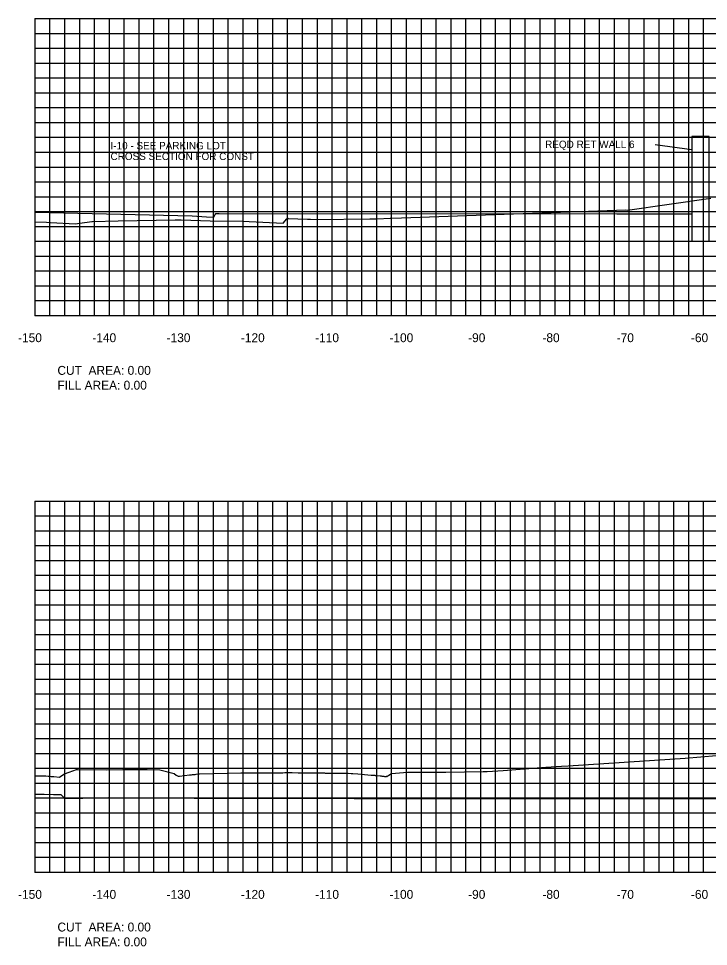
# Model space of a CAD drawing. Extents: x 1800880 to 1814006, y 250083 to 250560.
# Drawn here: x 1811658.8 to 1811751.7, y 250089.4 to 250214.4 of the extents above; entities that cross this region are included whole.
import ezdxf

# ---------------------------------------------------------------- set-up
doc = ezdxf.new("R2010")
doc.units = 0
for name, color, linetype in [('CL-CNST', 7, 'Continuous'), ('DESIGN - DRAINAGE - Bridges', 7, 'Continuous'), ('DRAINAGETXT', 7, 'Continuous'), ('EPTEXT', 7, 'Continuous'), ('Level 46', 7, 'Continuous'), ('Level 62', 7, 'Continuous')]:
    doc.layers.add(name, color=color, linetype=linetype)

msp = doc.modelspace()

# ---------------------------------------------------------------- linework, layer by layer
at = {"layer": 'CL-CNST'}
for points in [[(1811661, 250187.06), (1811662.51, 250186.98), (1811663.08, 250186.96), (1811666.44, 250186.78), (1811666.96, 250186.88), (1811667.04, 250186.87), (1811668.63, 250187.08), (1811668.72, 250187.08), (1811672.16, 250187.2), (1811679.86, 250187.32), (1811680.02, 250187.32), (1811680.68, 250187.3), (1811684.57, 250187.17), (1811688.92, 250187.12), (1811694.39, 250186.86), (1811694.89, 250187.45), (1811694.99, 250187.53), (1811695.02, 250187.53), (1811695.03, 250187.52), (1811695.05, 250187.49), (1811697.68, 250187.4), (1811698.08, 250187.39), (1811699.02, 250187.36), (1811706.06, 250187.45), (1811706.54, 250187.45), (1811707.03, 250187.45), (1811708.79, 250187.54), (1811708.87, 250187.54), (1811710.35, 250187.6), (1811740.52, 250188.64), (1811740.75, 250188.63), (1811751.98, 250190.23)], [(1811661, 250112.39), (1811661.42, 250112.39), (1811661.63, 250112.39), (1811662.39, 250112.38), (1811662.46, 250112.38), (1811662.74, 250112.36), (1811662.97, 250112.34), (1811663.16, 250112.33), (1811663.24, 250112.32), (1811663.29, 250112.32), (1811663.38, 250112.31), (1811663.45, 250112.3), (1811663.52, 250112.29), (1811664.28, 250112.22), (1811664.47, 250112.36), (1811664.95, 250112.68), (1811665.6, 250112.9), (1811666.57, 250113.24), (1811666.69, 250113.25), (1811670.61, 250113.2), (1811672.83, 250113.24), (1811672.93, 250113.24), (1811674.73, 250113.24), (1811675.11, 250113.24), (1811675.3, 250113.25), (1811676.04, 250113.25), (1811676.1, 250113.26), (1811677.79, 250113.19), (1811679.74, 250112.73), (1811680, 250112.49), (1811680.28, 250112.34), (1811680.34, 250112.34), (1811680.46, 250112.35), (1811681.77, 250112.52), (1811681.95, 250112.54), (1811681.98, 250112.54), (1811682.07, 250112.54), (1811682.2, 250112.59), (1811682.24, 250112.59), (1811682.35, 250112.58), (1811682.51, 250112.57), (1811682.56, 250112.58), (1811682.7, 250112.62), (1811682.98, 250112.65), (1811683.12, 250112.67), (1811688.7, 250112.79), (1811690.25, 250112.82), (1811690.32, 250112.82), (1811690.69, 250112.82), (1811690.75, 250112.82), (1811690.98, 250112.82), (1811691.19, 250112.82), (1811691.2, 250112.82), (1811691.22, 250112.82), (1811691.23, 250112.82), (1811691.24, 250112.82), (1811691.26, 250112.82), (1811691.65, 250112.82), (1811694.33, 250112.81), (1811694.64, 250112.83), (1811694.78, 250112.83), (1811694.96, 250112.83), (1811695.59, 250112.84), (1811696.42, 250112.81), (1811699.94, 250112.79), (1811700.04, 250112.78), (1811700.38, 250112.77), (1811700.85, 250112.77), (1811700.96, 250112.77), (1811701.34, 250112.75), (1811701.55, 250112.75), (1811702.12, 250112.76), (1811702.5, 250112.76), (1811703, 250112.74), (1811703.13, 250112.74), (1811703.54, 250112.72), (1811703.76, 250112.72), (1811704.47, 250112.67), (1811706.23, 250112.5), (1811706.72, 250112.47), (1811706.74, 250112.47), (1811706.75, 250112.47), (1811706.79, 250112.46), (1811706.82, 250112.46), (1811706.84, 250112.46), (1811706.88, 250112.46), (1811706.92, 250112.46), (1811706.95, 250112.45), (1811706.98, 250112.45), (1811707.01, 250112.45), (1811707.44, 250112.39), (1811707.58, 250112.38), (1811707.7, 250112.36), (1811707.82, 250112.35), (1811707.93, 250112.34), (1811708.03, 250112.33), (1811708.13, 250112.32), (1811708.22, 250112.31), (1811708.29, 250112.3), (1811708.3, 250112.32), (1811708.34, 250112.39), (1811708.37, 250112.3), (1811708.63, 250112.48), (1811709, 250112.72), (1811711.12, 250112.91), (1811715.93, 250112.9), (1811716.07, 250112.9), (1811716.29, 250112.9), (1811721.32, 250113), (1811721.39, 250113), (1811721.84, 250113), (1811724.02, 250113.13), (1811729.75, 250113.55), (1811731.86, 250113.7), (1811732.75, 250113.76), (1811748.54, 250114.79), (1811754.84, 250115.33)]]:
    msp.add_lwpolyline(points, dxfattribs=at)
at = {"layer": 'DESIGN - DRAINAGE - Bridges'}
for p, q in [((1811660.94, 250214.43), (1811661, 250214.43)), ((1811661, 250174.43), (1811661, 250214.43)), ((1811660.94, 250204.43), (1811661, 250204.43)), ((1811660.94, 250194.43), (1811661, 250194.43)), ((1811660.94, 250184.43), (1811661, 250184.43)), ((1811660.94, 250174.43), (1811661, 250174.43)), ((1811661, 250174.43), (1811961, 250174.43)), ((1811661, 250174.37), (1811661, 250174.43)), ((1811671, 250174.37), (1811671, 250174.43)), ((1811681, 250174.37), (1811681, 250174.43)), ((1811691, 250174.37), (1811691, 250174.43)), ((1811701, 250174.37), (1811701, 250174.43)), ((1811711, 250174.37), (1811711, 250174.43)), ((1811721, 250174.37), (1811721, 250174.43)), ((1811731, 250174.37), (1811731, 250174.43)), ((1811741, 250174.37), (1811741, 250174.43)), ((1811751, 250174.37), (1811751, 250174.43)), ((1811660.94, 250149.43), (1811661, 250149.43)), ((1811661, 250099.43), (1811661, 250149.43)), ((1811660.94, 250139.43), (1811661, 250139.43)), ((1811660.94, 250129.43), (1811661, 250129.43)), ((1811660.94, 250119.43), (1811661, 250119.43)), ((1811660.94, 250109.43), (1811661, 250109.43)), ((1811660.94, 250099.43), (1811661, 250099.43)), ((1811661, 250099.43), (1811961, 250099.43)), ((1811661, 250099.37), (1811661, 250099.43)), ((1811671, 250099.37), (1811671, 250099.43)), ((1811681, 250099.37), (1811681, 250099.43)), ((1811691, 250099.37), (1811691, 250099.43)), ((1811701, 250099.37), (1811701, 250099.43)), ((1811711, 250099.37), (1811711, 250099.43)), ((1811721, 250099.37), (1811721, 250099.43)), ((1811731, 250099.37), (1811731, 250099.43)), ((1811741, 250099.37), (1811741, 250099.43)), ((1811751, 250099.37), (1811751, 250099.43))]:
    msp.add_line(p, q, dxfattribs=at)
at = {"layer": 'EPTEXT'}
msp.add_line((1811744.46, 250197.48), (1811749.42, 250196.81), dxfattribs=at)
at = {"layer": 'Level 46'}
for p, q in [((1811661, 250214.43), (1811961, 250214.43)), ((1811661, 250174.43), (1811661, 250214.43)), ((1811663, 250174.43), (1811663, 250214.43)), ((1811665, 250174.43), (1811665, 250214.43)), ((1811667, 250174.43), (1811667, 250214.43)), ((1811669, 250174.43), (1811669, 250214.43)), ((1811671, 250174.43), (1811671, 250214.43)), ((1811673, 250174.43), (1811673, 250214.43)), ((1811675, 250174.43), (1811675, 250214.43)), ((1811677, 250174.43), (1811677, 250214.43)), ((1811679, 250174.43), (1811679, 250214.43)), ((1811681, 250174.43), (1811681, 250214.43)), ((1811683, 250174.43), (1811683, 250214.43)), ((1811685, 250174.43), (1811685, 250214.43)), ((1811687, 250174.43), (1811687, 250214.43)), ((1811689, 250174.43), (1811689, 250214.43)), ((1811691, 250174.43), (1811691, 250214.43)), ((1811693, 250174.43), (1811693, 250214.43)), ((1811695, 250174.43), (1811695, 250214.43)), ((1811697, 250174.43), (1811697, 250214.43)), ((1811699, 250174.43), (1811699, 250214.43)), ((1811701, 250174.43), (1811701, 250214.43)), ((1811703, 250174.43), (1811703, 250214.43)), ((1811705, 250174.43), (1811705, 250214.43)), ((1811707, 250174.43), (1811707, 250214.43)), ((1811709, 250174.43), (1811709, 250214.43)), ((1811711, 250174.43), (1811711, 250214.43)), ((1811713, 250174.43), (1811713, 250214.43)), ((1811715, 250174.43), (1811715, 250214.43)), ((1811717, 250174.43), (1811717, 250214.43)), ((1811719, 250174.43), (1811719, 250214.43)), ((1811721, 250174.43), (1811721, 250214.43)), ((1811723, 250174.43), (1811723, 250214.43)), ((1811725, 250174.43), (1811725, 250214.43)), ((1811727, 250174.43), (1811727, 250214.43)), ((1811729, 250174.43), (1811729, 250214.43)), ((1811731, 250174.43), (1811731, 250214.43)), ((1811733, 250174.43), (1811733, 250214.43)), ((1811735, 250174.43), (1811735, 250214.43)), ((1811737, 250174.43), (1811737, 250214.43)), ((1811739, 250174.43), (1811739, 250214.43)), ((1811741, 250174.43), (1811741, 250214.43)), ((1811743, 250174.43), (1811743, 250214.43)), ((1811745, 250174.43), (1811745, 250214.43)), ((1811747, 250174.43), (1811747, 250214.43)), ((1811749, 250174.43), (1811749, 250214.43)), ((1811751, 250174.43), (1811751, 250214.43)), ((1811661, 250212.43), (1811961, 250212.43)), ((1811661, 250210.43), (1811961, 250210.43)), ((1811661, 250208.43), (1811961, 250208.43)), ((1811661, 250206.43), (1811961, 250206.43)), ((1811661, 250204.43), (1811961, 250204.43)), ((1811661, 250202.43), (1811961, 250202.43)), ((1811661, 250200.43), (1811961, 250200.43)), ((1811661, 250198.43), (1811961, 250198.43)), ((1811661, 250196.43), (1811961, 250196.43)), ((1811661, 250194.43), (1811961, 250194.43)), ((1811661, 250192.43), (1811961, 250192.43)), ((1811661, 250190.43), (1811961, 250190.43)), ((1811661, 250188.43), (1811961, 250188.43)), ((1811661, 250186.43), (1811961, 250186.43)), ((1811661, 250184.43), (1811961, 250184.43)), ((1811661, 250182.43), (1811961, 250182.43)), ((1811661, 250180.43), (1811961, 250180.43)), ((1811661, 250178.43), (1811961, 250178.43)), ((1811661, 250176.43), (1811961, 250176.43)), ((1811661, 250174.43), (1811961, 250174.43)), ((1811661, 250149.43), (1811961, 250149.43)), ((1811661, 250099.43), (1811661, 250149.43)), ((1811663, 250099.43), (1811663, 250149.43)), ((1811665, 250099.43), (1811665, 250149.43)), ((1811667, 250099.43), (1811667, 250149.43)), ((1811669, 250099.43), (1811669, 250149.43)), ((1811671, 250099.43), (1811671, 250149.43)), ((1811673, 250099.43), (1811673, 250149.43)), ((1811675, 250099.43), (1811675, 250149.43)), ((1811677, 250099.43), (1811677, 250149.43)), ((1811679, 250099.43), (1811679, 250149.43)), ((1811681, 250099.43), (1811681, 250149.43)), ((1811683, 250099.43), (1811683, 250149.43)), ((1811685, 250099.43), (1811685, 250149.43)), ((1811687, 250099.43), (1811687, 250149.43)), ((1811689, 250099.43), (1811689, 250149.43)), ((1811691, 250099.43), (1811691, 250149.43)), ((1811693, 250099.43), (1811693, 250149.43)), ((1811695, 250099.43), (1811695, 250149.43)), ((1811697, 250099.43), (1811697, 250149.43)), ((1811699, 250099.43), (1811699, 250149.43)), ((1811701, 250099.43), (1811701, 250149.43)), ((1811703, 250099.43), (1811703, 250149.43)), ((1811705, 250099.43), (1811705, 250149.43)), ((1811707, 250099.43), (1811707, 250149.43)), ((1811709, 250099.43), (1811709, 250149.43)), ((1811711, 250099.43), (1811711, 250149.43)), ((1811713, 250099.43), (1811713, 250149.43)), ((1811715, 250099.43), (1811715, 250149.43)), ((1811717, 250099.43), (1811717, 250149.43)), ((1811719, 250099.43), (1811719, 250149.43)), ((1811721, 250099.43), (1811721, 250149.43)), ((1811723, 250099.43), (1811723, 250149.43)), ((1811725, 250099.43), (1811725, 250149.43)), ((1811727, 250099.43), (1811727, 250149.43)), ((1811729, 250099.43), (1811729, 250149.43)), ((1811731, 250099.43), (1811731, 250149.43)), ((1811733, 250099.43), (1811733, 250149.43)), ((1811735, 250099.43), (1811735, 250149.43)), ((1811737, 250099.43), (1811737, 250149.43)), ((1811739, 250099.43), (1811739, 250149.43)), ((1811741, 250099.43), (1811741, 250149.43)), ((1811743, 250099.43), (1811743, 250149.43)), ((1811745, 250099.43), (1811745, 250149.43)), ((1811747, 250099.43), (1811747, 250149.43)), ((1811749, 250099.43), (1811749, 250149.43)), ((1811751, 250099.43), (1811751, 250149.43)), ((1811661, 250147.43), (1811961, 250147.43)), ((1811661, 250145.43), (1811961, 250145.43)), ((1811661, 250143.43), (1811961, 250143.43)), ((1811661, 250141.43), (1811961, 250141.43)), ((1811661, 250139.43), (1811961, 250139.43)), ((1811661, 250137.43), (1811961, 250137.43)), ((1811661, 250135.43), (1811961, 250135.43)), ((1811661, 250133.43), (1811961, 250133.43)), ((1811661, 250131.43), (1811961, 250131.43)), ((1811661, 250129.43), (1811961, 250129.43)), ((1811661, 250127.43), (1811961, 250127.43)), ((1811661, 250125.43), (1811961, 250125.43)), ((1811661, 250123.43), (1811961, 250123.43)), ((1811661, 250121.43), (1811961, 250121.43)), ((1811661, 250119.43), (1811961, 250119.43)), ((1811661, 250117.43), (1811961, 250117.43)), ((1811661, 250115.43), (1811961, 250115.43)), ((1811661, 250113.43), (1811961, 250113.43)), ((1811661, 250111.43), (1811961, 250111.43)), ((1811661, 250109.43), (1811961, 250109.43)), ((1811661, 250107.43), (1811961, 250107.43)), ((1811661, 250105.43), (1811961, 250105.43)), ((1811661, 250103.43), (1811961, 250103.43)), ((1811661, 250101.43), (1811961, 250101.43)), ((1811661, 250099.43), (1811961, 250099.43))]:
    msp.add_line(p, q, dxfattribs=at)
at = {"layer": 'Level 62'}
msp.add_lwpolyline([(1811749.42, 250184.43), (1811751.75, 250184.43), (1811751.75, 250198.52), (1811749.42, 250198.52)], close=True, dxfattribs=at)
for points in [[(1811661, 250188.35), (1811682.14, 250187.86), (1811684.08, 250187.74), (1811685.07, 250187.68), (1811685.23, 250188.01), (1811685.31, 250188.18), (1811685.63, 250188.17), (1811685.8, 250188.17), (1811739.34, 250188.11), (1811749.42, 250188.1)], [(1811661, 250109.94), (1811662.2, 250109.91), (1811663.49, 250109.88), (1811663.76, 250109.88), (1811664.46, 250109.87), (1811664.8, 250109.52), (1811664.95, 250109.36), (1811667.4, 250109.4), (1811670.85, 250109.46), (1811682.4, 250109.41), (1811682.64, 250109.41), (1811682.95, 250109.41), (1811683.25, 250109.41), (1811683.25, 250109.41), (1811703.94, 250109.36), (1811709.53, 250109.35), (1811719.22, 250109.34), (1811736.1, 250109.33), (1811755.39, 250109.34)]]:
    msp.add_lwpolyline(points, dxfattribs=at)

# ---------------------------------------------------------------- texts
for s, p in [('-150', (1811658.7, 250170.83)), ('-140', (1811668.7, 250170.83)), ('-130', (1811678.7, 250170.83)), ('-120', (1811688.7, 250170.83)), ('-110', (1811698.7, 250170.83)), ('-100', (1811708.7, 250170.83)), ('-90', (1811719.3, 250170.83)), ('-80', (1811729.3, 250170.83)), ('-70', (1811739.3, 250170.83)), ('-60', (1811749.3, 250170.83)), ('-150', (1811658.7, 250095.83)), ('-140', (1811668.7, 250095.83)), ('-130', (1811678.7, 250095.83)), ('-120', (1811688.7, 250095.83)), ('-110', (1811698.7, 250095.83)), ('-100', (1811708.7, 250095.83)), ('-90', (1811719.3, 250095.83)), ('-80', (1811729.3, 250095.83)), ('-70', (1811739.3, 250095.83)), ('-60', (1811749.3, 250095.83))]:
    msp.add_text(s, height=1.2).set_placement(p)
at = {"layer": 'DESIGN - DRAINAGE - Bridges'}
for p in [(1811661, 250174.43), (1811661, 250099.43)]:
    msp.add_text('-', height=0.0001, dxfattribs=at).set_placement(p)
at = {"layer": 'DRAINAGETXT'}
for s, p in [('CUT  AREA: 0.00', (1811664, 250166.43)), ('FILL AREA: 0.00', (1811664, 250164.43)), ('CUT  AREA: 0.00', (1811664, 250091.43)), ('FILL AREA: 0.00', (1811664, 250089.43))]:
    msp.add_text(s, height=1.2, dxfattribs=at).set_placement(p)
at = {"layer": 'EPTEXT'}
for s, p in [('REQD RET WALL 6', (1811729.67, 250196.98)), ('I-10 - SEE PARKING LOT', (1811671.15, 250196.81)), ('CROSS SECTION FOR CONST ', (1811671.15, 250195.37))]:
    msp.add_text(s, height=1, dxfattribs=at).set_placement(p)

doc.saveas('drawing.dxf')
